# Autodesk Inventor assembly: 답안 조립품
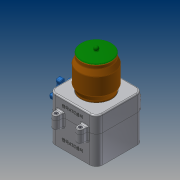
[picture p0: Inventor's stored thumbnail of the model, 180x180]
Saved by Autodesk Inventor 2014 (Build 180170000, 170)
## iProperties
Created: 2018-01
Part Number: 답안 조립품
Document SubType Name: Assembly
Designer: user
Author: user
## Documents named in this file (9)
- C:\Users\user\Desktop\480108V1022\답안 조립품.iam
- C:\Users\user\Desktop\480108V1022\본체.ipt
- C:\Users\user\Desktop\480108V1022\핸들축.ipt
- C:\Users\user\Desktop\480108V1022\핸들.ipt
- C:\Users\user\Desktop\480108V1022\볼트 M3x12.ipt
- C:\Users\user\Desktop\480108V1022\본체커버.ipt
- C:\Users\user\Desktop\480108V1022\용기.ipt
- C:\Users\user\Desktop\480108V1022\용기캡.ipt
- C:\Users\user\Desktop\480108V1022\볼트 M4x12.ipt
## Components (2 placed, 2 different names)
1. 핸들축:1
2. 핸들:1
